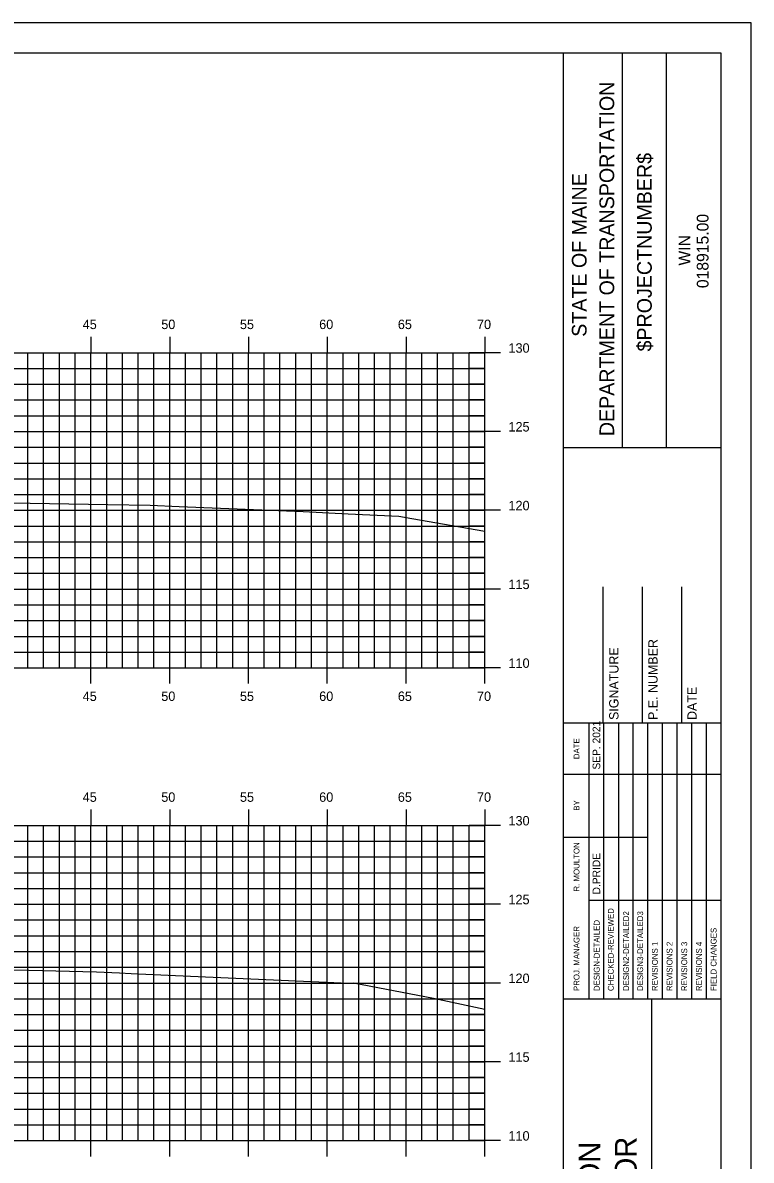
# Model space of a CAD drawing. Extents: x 853069 to 853241, y 365624 to 365734.
# Drawn here: x 853192.7 to 853239, y 365661.8 to 365734 of the extents above; entities that cross this region are included whole.
import ezdxf

# ---------------------------------------------------------------- set-up
doc = ezdxf.new("R2010")
doc.units = 0
for name, color, linetype in [('BORDER', 7, 'Continuous'), ('H_V ANNOTATION', 7, 'Continuous'), ('M_Roadway_Centerline', 7, 'Continuous'), ('MAJOR', 7, 'Continuous'), ('MINOR', 7, 'Continuous'), ('PLOT BOUNDARY', 7, 'Continuous'), ('S_Roadway_Centerline', 7, 'Continuous')]:
    doc.layers.add(name, color=color, linetype=linetype)

msp = doc.modelspace()

# ---------------------------------------------------------------- linework, layer by layer
at = {"layer": 'BORDER'}
for p, q in [((853227.062, 365627.027), (853227.062, 365732.027)), ((853230.79, 365707.024), (853230.79, 365732.024)), ((853233.585, 365707.024), (853233.585, 365732.024)), ((853227.063, 365707.021), (853237.062, 365707.021)), ((853229.562, 365689.53), (853229.562, 365698.177)), ((853232.062, 365689.53), (853232.062, 365698.177)), ((853234.562, 365689.53), (853234.562, 365698.177)), ((853227.062, 365689.53), (853237.062, 365689.53)), ((853227.062, 365672.03), (853237.062, 365672.03)), ((853232.653, 365637.03), (853232.653, 365672.03))]:
    msp.add_line(p, q, dxfattribs=at)
msp.add_lwpolyline([(853077.062, 365627.027), (853237.062, 365627.027), (853237.062, 365732.027), (853077.062, 365732.027)], close=True, dxfattribs=at)
for points in [[(853228.677, 365686.28), (853228.677, 365689.53)], [(853229.609, 365672.033), (853229.609, 365689.53)], [(853230.541, 365689.53), (853230.541, 365672.033)], [(853231.472, 365672.033), (853231.472, 365689.53)], [(853232.404, 365672.033), (853232.404, 365689.53)], [(853233.336, 365672.033), (853233.336, 365689.53)], [(853234.268, 365672.033), (853234.268, 365689.53)], [(853235.199, 365672.033), (853235.199, 365689.53)], [(853236.131, 365672.033), (853236.131, 365689.53)], [(853228.677, 365672.033), (853228.677, 365688.824)], [(853227.062, 365686.28), (853237.062, 365686.28)], [(853227.062, 365682.28), (853228.677, 365682.28)], [(853228.677, 365682.28), (853232.403, 365682.28)], [(853228.677, 365678.28), (853237.062, 365678.28)]]:
    msp.add_lwpolyline(points, dxfattribs=at)
at = {"layer": 'MAJOR'}
for p, q in [((853197.061, 365714.029), (853197.061, 365713.027)), ((853202.061, 365714.029), (853202.061, 365713.027)), ((853207.061, 365714.029), (853207.061, 365713.027)), ((853212.061, 365714.029), (853212.061, 365713.027)), ((853217.061, 365714.029), (853217.061, 365713.027)), ((853222.061, 365714.029), (853222.061, 365713.027)), ((853082.061, 365713.027), (853222.061, 365713.027)), ((853082.061, 365713.027), (853222.061, 365713.027)), ((853197.061, 365693.027), (853197.061, 365713.027)), ((853202.061, 365693.027), (853202.061, 365713.027)), ((853207.061, 365693.027), (853207.061, 365713.027)), ((853212.061, 365693.027), (853212.061, 365713.027)), ((853217.061, 365693.027), (853217.061, 365713.027)), ((853223.063, 365713.027), (853221.059, 365713.027)), ((853222.061, 365693.027), (853222.061, 365713.027)), ((853222.061, 365693.027), (853222.061, 365713.027)), ((853082.061, 365708.027), (853222.061, 365708.027)), ((853223.063, 365708.027), (853221.059, 365708.027)), ((853082.061, 365703.027), (853222.061, 365703.027)), ((853223.063, 365703.027), (853221.059, 365703.027)), ((853082.061, 365698.027), (853222.061, 365698.027)), ((853223.063, 365698.027), (853221.059, 365698.027)), ((853082.061, 365693.027), (853222.061, 365693.027)), ((853082.061, 365693.027), (853222.061, 365693.027)), ((853197.061, 365692.025), (853197.061, 365693.027)), ((853202.061, 365692.025), (853202.061, 365693.027)), ((853207.061, 365692.025), (853207.061, 365693.027)), ((853212.061, 365692.025), (853212.061, 365693.027)), ((853217.061, 365692.025), (853217.061, 365693.027)), ((853223.063, 365693.027), (853221.059, 365693.027)), ((853222.061, 365692.025), (853222.061, 365693.027)), ((853197.061, 365684.029), (853197.061, 365683.027)), ((853202.061, 365684.029), (853202.061, 365683.027)), ((853207.061, 365684.029), (853207.061, 365683.027)), ((853212.061, 365684.029), (853212.061, 365683.027)), ((853217.061, 365684.029), (853217.061, 365683.027)), ((853222.061, 365684.029), (853222.061, 365683.027)), ((853082.061, 365683.027), (853222.061, 365683.027)), ((853082.061, 365683.027), (853222.061, 365683.027)), ((853197.061, 365663.027), (853197.061, 365683.027)), ((853202.061, 365663.027), (853202.061, 365683.027)), ((853207.061, 365663.027), (853207.061, 365683.027)), ((853212.061, 365663.027), (853212.061, 365683.027)), ((853217.061, 365663.027), (853217.061, 365683.027)), ((853223.063, 365683.027), (853221.059, 365683.027)), ((853222.061, 365663.027), (853222.061, 365683.027)), ((853222.061, 365663.027), (853222.061, 365683.027)), ((853082.061, 365678.027), (853222.061, 365678.027)), ((853223.063, 365678.027), (853221.059, 365678.027)), ((853082.061, 365673.027), (853222.061, 365673.027)), ((853223.063, 365673.027), (853221.059, 365673.027)), ((853082.061, 365668.027), (853222.061, 365668.027)), ((853223.063, 365668.027), (853221.059, 365668.027)), ((853082.061, 365663.027), (853222.061, 365663.027)), ((853082.061, 365663.027), (853222.061, 365663.027)), ((853197.061, 365662.025), (853197.061, 365663.027)), ((853202.061, 365662.025), (853202.061, 365663.027)), ((853207.061, 365662.025), (853207.061, 365663.027)), ((853212.061, 365662.025), (853212.061, 365663.027)), ((853217.061, 365662.025), (853217.061, 365663.027)), ((853223.063, 365663.027), (853221.059, 365663.027)), ((853222.061, 365662.025), (853222.061, 365663.027))]:
    msp.add_line(p, q, dxfattribs=at)
at = {"layer": 'MINOR'}
for p, q in [((853193.061, 365693.027), (853193.061, 365713.027)), ((853194.061, 365693.027), (853194.061, 365713.027)), ((853195.061, 365693.027), (853195.061, 365713.027)), ((853196.061, 365693.027), (853196.061, 365713.027)), ((853198.061, 365693.027), (853198.061, 365713.027)), ((853199.061, 365693.027), (853199.061, 365713.027)), ((853200.061, 365693.027), (853200.061, 365713.027)), ((853201.061, 365693.027), (853201.061, 365713.027)), ((853203.061, 365693.027), (853203.061, 365713.027)), ((853204.061, 365693.027), (853204.061, 365713.027)), ((853205.061, 365693.027), (853205.061, 365713.027)), ((853206.061, 365693.027), (853206.061, 365713.027)), ((853208.061, 365693.027), (853208.061, 365713.027)), ((853209.061, 365693.027), (853209.061, 365713.027)), ((853210.061, 365693.027), (853210.061, 365713.027)), ((853211.061, 365693.027), (853211.061, 365713.027)), ((853213.061, 365693.027), (853213.061, 365713.027)), ((853214.061, 365693.027), (853214.061, 365713.027)), ((853215.061, 365693.027), (853215.061, 365713.027)), ((853216.061, 365693.027), (853216.061, 365713.027)), ((853218.061, 365693.027), (853218.061, 365713.027)), ((853219.061, 365693.027), (853219.061, 365713.027)), ((853220.061, 365693.027), (853220.061, 365713.027)), ((853221.061, 365693.027), (853221.061, 365713.027)), ((853082.061, 365712.027), (853222.061, 365712.027)), ((853222.061, 365712.027), (853221.059, 365712.027)), ((853082.061, 365711.027), (853222.061, 365711.027)), ((853222.061, 365711.027), (853221.059, 365711.027)), ((853082.061, 365710.027), (853222.061, 365710.027)), ((853222.061, 365710.027), (853221.059, 365710.027)), ((853082.061, 365709.027), (853222.061, 365709.027)), ((853222.061, 365709.027), (853221.059, 365709.027)), ((853082.061, 365707.027), (853222.061, 365707.027)), ((853222.061, 365707.027), (853221.059, 365707.027)), ((853082.061, 365706.027), (853222.061, 365706.027)), ((853222.061, 365706.027), (853221.059, 365706.027)), ((853082.061, 365705.027), (853222.061, 365705.027)), ((853222.061, 365705.027), (853221.059, 365705.027)), ((853082.061, 365704.027), (853222.061, 365704.027)), ((853222.061, 365704.027), (853221.059, 365704.027)), ((853082.061, 365702.027), (853222.061, 365702.027)), ((853222.061, 365702.027), (853221.059, 365702.027)), ((853082.061, 365701.027), (853222.061, 365701.027)), ((853222.061, 365701.027), (853221.059, 365701.027)), ((853082.061, 365700.027), (853222.061, 365700.027)), ((853222.061, 365700.027), (853221.059, 365700.027)), ((853082.061, 365699.027), (853222.061, 365699.027)), ((853222.061, 365699.027), (853221.059, 365699.027)), ((853082.061, 365697.027), (853222.061, 365697.027)), ((853222.061, 365697.027), (853221.059, 365697.027)), ((853082.061, 365696.027), (853222.061, 365696.027)), ((853222.061, 365696.027), (853221.059, 365696.027)), ((853082.061, 365695.027), (853222.061, 365695.027)), ((853222.061, 365695.027), (853221.059, 365695.027)), ((853082.061, 365694.027), (853222.061, 365694.027)), ((853222.061, 365694.027), (853221.059, 365694.027)), ((853193.061, 365663.027), (853193.061, 365683.027)), ((853194.061, 365663.027), (853194.061, 365683.027)), ((853195.061, 365663.027), (853195.061, 365683.027)), ((853196.061, 365663.027), (853196.061, 365683.027)), ((853198.061, 365663.027), (853198.061, 365683.027)), ((853199.061, 365663.027), (853199.061, 365683.027)), ((853200.061, 365663.027), (853200.061, 365683.027)), ((853201.061, 365663.027), (853201.061, 365683.027)), ((853203.061, 365663.027), (853203.061, 365683.027)), ((853204.061, 365663.027), (853204.061, 365683.027)), ((853205.061, 365663.027), (853205.061, 365683.027)), ((853206.061, 365663.027), (853206.061, 365683.027)), ((853208.061, 365663.027), (853208.061, 365683.027)), ((853209.061, 365663.027), (853209.061, 365683.027)), ((853210.061, 365663.027), (853210.061, 365683.027)), ((853211.061, 365663.027), (853211.061, 365683.027)), ((853213.061, 365663.027), (853213.061, 365683.027)), ((853214.061, 365663.027), (853214.061, 365683.027)), ((853215.061, 365663.027), (853215.061, 365683.027)), ((853216.061, 365663.027), (853216.061, 365683.027)), ((853218.061, 365663.027), (853218.061, 365683.027)), ((853219.061, 365663.027), (853219.061, 365683.027)), ((853220.061, 365663.027), (853220.061, 365683.027)), ((853221.061, 365663.027), (853221.061, 365683.027)), ((853082.061, 365682.027), (853222.061, 365682.027)), ((853222.061, 365682.027), (853221.059, 365682.027)), ((853082.061, 365681.027), (853222.061, 365681.027)), ((853222.061, 365681.027), (853221.059, 365681.027)), ((853082.061, 365680.027), (853222.061, 365680.027)), ((853222.061, 365680.027), (853221.059, 365680.027)), ((853082.061, 365679.027), (853222.061, 365679.027)), ((853222.061, 365679.027), (853221.059, 365679.027)), ((853082.061, 365677.027), (853222.061, 365677.027)), ((853222.061, 365677.027), (853221.059, 365677.027)), ((853082.061, 365676.027), (853222.061, 365676.027)), ((853222.061, 365676.027), (853221.059, 365676.027)), ((853082.061, 365675.027), (853222.061, 365675.027)), ((853222.061, 365675.027), (853221.059, 365675.027)), ((853082.061, 365674.027), (853222.061, 365674.027)), ((853222.061, 365674.027), (853221.059, 365674.027)), ((853082.061, 365672.027), (853222.061, 365672.027)), ((853222.061, 365672.027), (853221.059, 365672.027)), ((853082.061, 365671.027), (853222.061, 365671.027)), ((853222.061, 365671.027), (853221.059, 365671.027)), ((853082.061, 365670.027), (853222.061, 365670.027)), ((853222.061, 365670.027), (853221.059, 365670.027)), ((853082.061, 365669.027), (853222.061, 365669.027)), ((853222.061, 365669.027), (853221.059, 365669.027)), ((853082.061, 365667.027), (853222.061, 365667.027)), ((853222.061, 365667.027), (853221.059, 365667.027)), ((853082.061, 365666.027), (853222.061, 365666.027)), ((853222.061, 365666.027), (853221.059, 365666.027)), ((853082.061, 365665.027), (853222.061, 365665.027)), ((853222.061, 365665.027), (853221.059, 365665.027)), ((853082.061, 365664.027), (853222.061, 365664.027)), ((853222.061, 365664.027), (853221.059, 365664.027))]:
    msp.add_line(p, q, dxfattribs=at)
at = {"layer": 'PLOT BOUNDARY'}
msp.add_lwpolyline([(853068.968, 365623.968), (853238.968, 365623.968), (853238.968, 365733.968), (853068.968, 365733.968)], close=True, dxfattribs=at)
at = {"layer": 'S_Roadway_Centerline'}
for points in [[(853146.06, 365701.731), (853151.328, 365702.256), (853152.994, 365702.38), (853158.079, 365702.873), (853162.653, 365703.022), (853164.622, 365703.056), (853167.031, 365703.152), (853170.662, 365703.317), (853174.584, 365703.403), (853176.358, 365703.45), (853185.171, 365703.516), (853188.597, 365703.568), (853190.719, 365703.529), (853198.136, 365703.398), (853200.822, 365703.355), (853202.664, 365703.261), (853210.529, 365702.943), (853213.394, 365702.811), (853216.608, 365702.648), (853217.427, 365702.514), (853222.061, 365701.7)], [(853140.919, 365671.697), (853160.13, 365673.253), (853160.468, 365673.285), (853160.611, 365673.288), (853163.848, 365673.373), (853169.878, 365673.576), (853173.583, 365673.698), (853175.863, 365673.749), (853178.131, 365673.789), (853187.551, 365673.905), (853193.111, 365673.835), (853197.409, 365673.744), (853198.878, 365673.668), (853199.61, 365673.64), (853202.439, 365673.501), (853213.429, 365673.011), (853213.719, 365673.043), (853218.8, 365672.06), (853222.061, 365671.378)]]:
    msp.add_lwpolyline(points, dxfattribs=at)

# ---------------------------------------------------------------- texts
at = {"layer": 'BORDER'}
for s, height, p in [('DEPARTMENT OF TRANSPORTATION', 0.93176, (853230.269, 365707.733)), ('$PROJECTNUMBER$', 0.93176, (853232.654, 365713.106)), ('STATE OF MAINE', 0.93176, (853228.517, 365714.039)), ('018915.00', 0.7453, (853236.257, 365717.125)), ('WIN', 0.7453, (853235.098, 365718.557)), ('P.E. NUMBER', 0.59055, (853233.022, 365689.722)), ('SIGNATURE', 0.5906, (853230.542, 365689.722)), ('DATE', 0.5906, (853235.503, 365689.722)), ('SEP. 2021', 0.4845, (853229.384, 365686.575)), ('DATE', 0.3714, (853228.066, 365687.235)), ('BY', 0.3714, (853228.066, 365683.965)), ('R. MOULTON', 0.3727, (853228.065, 365678.832)), ('D.PRIDE', 0.4845, (853229.384, 365678.653)), ('CHECKED-REVIEWED', 0.37275, (853230.243, 365672.518)), ('DESIGN2-DETAILED2', 0.37275, (853231.212, 365672.518)), ('DESIGN3-DETAILED3', 0.37275, (853232.106, 365672.518)), ('DESIGN-DETAILED', 0.37275, (853229.348, 365672.518)), ('PROJ. MANAGER', 0.37275, (853228.066, 365672.518)), ('FIELD CHANGES', 0.37275, (853236.764, 365672.518)), ('REVISIONS 1', 0.37275, (853233.038, 365672.518)), ('REVISIONS 2', 0.37275, (853233.969, 365672.518)), ('REVISIONS 3', 0.37275, (853234.901, 365672.518)), ('REVISIONS 4', 0.37275, (853235.833, 365672.518)), ('I-395/ROUTE 9 CONNECTOR', 1.37787, (853231.696, 365638.192)), ('BREWER TO EDDINGTON', 1.37787, (853229.395, 365640.231))]:
    msp.add_text(s, height=height, rotation=90, dxfattribs=at).set_placement(p)
at = {"layer": 'H_V ANNOTATION'}
for s, p in [('45', (853196.54, 365714.527)), ('50', (853201.526, 365714.527)), ('55', (853206.518, 365714.527)), ('60', (853211.548, 365714.527)), ('65', (853216.54, 365714.527)), ('70', (853221.564, 365714.527)), ('130', (853223.561, 365713.027)), ('125', (853223.561, 365708.027)), ('120', (853223.561, 365703.027)), ('115', (853223.561, 365698.027)), ('110', (853223.561, 365693.027)), ('45', (853196.54, 365690.927)), ('50', (853201.526, 365690.927)), ('55', (853206.518, 365690.927)), ('60', (853211.548, 365690.927)), ('65', (853216.54, 365690.927)), ('70', (853221.564, 365690.927)), ('45', (853196.54, 365684.527)), ('50', (853201.526, 365684.527)), ('55', (853206.518, 365684.527)), ('60', (853211.548, 365684.527)), ('65', (853216.54, 365684.527)), ('70', (853221.564, 365684.527)), ('130', (853223.561, 365683.027)), ('125', (853223.561, 365678.027)), ('120', (853223.561, 365673.027)), ('115', (853223.561, 365668.027)), ('110', (853223.561, 365663.027))]:
    msp.add_text(s, height=0.6, dxfattribs=at).set_placement(p)
at = {"layer": 'M_Roadway_Centerline'}
for s, p in [('C', (853200.817, 365703.355)), ('L', (853200.822, 365703.348)), ('C', (853197.404, 365673.744)), ('L', (853197.409, 365673.737))]:
    msp.add_text(s, height=0.0146, dxfattribs=at).set_placement(p)

doc.saveas('drawing.dxf')
